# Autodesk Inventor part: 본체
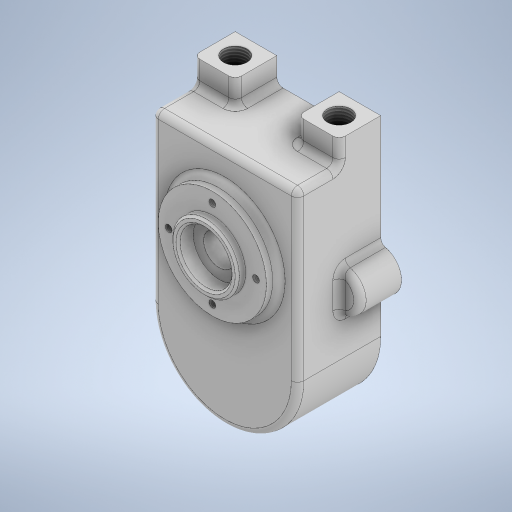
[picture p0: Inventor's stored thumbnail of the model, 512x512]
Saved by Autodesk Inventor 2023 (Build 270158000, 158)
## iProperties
Created: 2024-03
Part Number: 본체
Material: 일반
Document SubType Name: Modeling
Designer: asung
Density: 1 g/cm^3
Appearance: 기본값
Author: asung
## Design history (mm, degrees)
sketch "스케치1"
  geometry: L1 (-35, 40)-(35, 40); L2 (35, 40)-(35, -40); L3 (35, -40)-(-35, -40); L4 (-35, -40)-(-35, 40); L5 (-35, 40)-(35, -40); L6 (35, 40)-(-35, -40); A1 r 35 centre (0, -40) between (-35, -40) and (35, -40); 1 further point
  constraints: 12 end point, 2 midpoint, 2 parallel, 2 point on circle, 1 centre point, 1 horizontal, 1 perpendicular
  dimensions: "d0" = 70 distance of L2.end L3.end; "d1" = 80 distance of L1.end L2.end; "d2" = 35 radius of A1
extrude "돌출1" new body sketch "스케치1" distance "d3" = 40; taper "d4" = 0 deg
sketch "스케치2"
  geometry: L1 (-35, -40)-(-35, 40) reference; L2 (35, 40)-(35, -40) reference; L3 (-35, 40)-(35, 40) reference; L4 (0, 40)-(0, 0); L5 (0, 0)-(0, -40); L6 (-14, -11.314)-(-14, -28.686); L7 (14, -11.314)-(14, -28.686); A1 r 35 centre (0, -40) between (-35, -40) and (35, -40) reference; A2 r 18 centre (0, 0) between (14, -11.314) and (-14, -11.314); A3 r 18 centre (0, -40) between (-14, -28.686) and (14, -28.686); 3 further points
  constraints: 8 end point, 4 point on circle, 2 centre point, 2 coincident, 2 parallel, 2 vertical, 1 midpoint, 1 symmetric about line
  dimensions: "d12" = 40 distance of L4.start L4.end; "d13" = 36 diameter of A2; "d14" = 40 distance of L5.start L5.end (derived); "d15" = 36 diameter of A3; "d17" = 14 distance between parallel lines of L4 L7; "d18" = 28 distance between parallel lines of L6 L7; "d19" = 0 distance from line of point (14, -7) L7; "d20" = 0 distance from line of point (14, -35.376) L7; "d21" = 35.8469 distance of L5.end point (14, -7); "d22" = 14.74401 distance of L5.end point (14, -35.376)
extrude "돌출2" cut sketch "스케치2" distance "d23" = 20; taper "d24" = 0 deg
sketch "스케치3"
  geometry: L1 (70, -20)-(50, -20); L2 (50, -20)-(50, 0); L3 (50, 0)-(70, 0); L4 (70, 0)-(70, -20); L5 (70, 0)-(0, 0) reference; L6 (20, -20)-(0, -20); L7 (0, -20)-(0, 0); L8 (0, 0)-(20, 0); L9 (20, 0)-(20, -20); 3 further points
  constraints: 16 end point, 4 parallel, 2 horizontal, 2 perpendicular, 1 coincident, 1 midpoint, 1 point on line
  dimensions: "d25" = 20 distance of L2.end L3.end; "d26" = 20 distance of L1.end L2.end; "d27" = 20 distance of L5.end L8.end; "d28" = 20 distance of L5.end L6.end
extrude "돌출3" join sketch "스케치3" distance "d29" = 12; taper "d30" = 0 deg
fillet "모깎기1" dims "d31" = 3
fillet "모깎기2" dims "d32" = 3
sketch "스케치4"
  geometry: L1 (-14, -28.686)-(-14, -11.314) reference; L2 (14, -11.314)-(14, -28.686) reference; L3 (-35, -40)-(-35, 52) reference; L4 (35, -40)-(35, 52) reference; L5 (15, 52)-(35, 52) reference; L6 (15, 43)-(15, 52) reference; L7 (-12, 40)-(12, 40) reference; L8 (-15, 43)-(-15, 52) reference; L9 (-35, 52)-(-15, 52) reference; L10 (-35, 52)-(-35, -11.5); L11 (0, 40)-(0, 29.195); A1 r 18 centre (0, -40) between (-14, -28.686) and (14, -28.686) reference; A2 r 18 centre (0, 0) between (14, -11.314) and (-14, -11.314) reference; A3 r 35 centre (0, -40) between (-35, -40) and (35, -40) reference; A4 r 3 centre (12, 43) between (12, 40) and (15, 43) reference; A5 r 3 centre (-12, 43) between (-15, 43) and (-12, 40) reference; A6 r 10 centre (-35, -11.5) between (-35, -1.5) and (-35, -21.5); A7 r 10 centre (35, -11.5) between (35, -21.5) and (35, -1.5); 4 further points
  constraints: 4 end point, 4 point on circle, 3 point on line, 3 symmetric about line, 2 centre point, 1 coincident, 1 midpoint, 1 vertical, 1 other
  dimensions: "d33" = 63.5 distance of L3.end L10.end; "d34" = 10 radius of A6
extrude "돌출4" join sketch "스케치4" distance "d35" = 20; taper "d36" = 0 deg
fillet "모깎기3" dims "d37" = 3
fillet "모깎기4" dims "d38" = 3
sketch "스케치5"
  geometry: L1 (-14, -28.686)-(-14, -11.314) reference; L2 (14, -11.314)-(14, -28.686) reference; L3 (-35, -40)-(-35, -24.149) reference; L4 (35, -40)-(35, -24.149) reference; L5 (35, 1.149)-(35, 52) reference; L6 (15, 52)-(35, 52) reference; L7 (15, 43)-(15, 52) reference; L8 (-12, 40)-(12, 40) reference; L9 (-15, 43)-(-15, 52) reference; L10 (-35, 52)-(-15, 52) reference; L11 (-35, 1.149)-(-35, 52) reference; L12 (0, -40)-(0, -66); A1 r 18 centre (0, -40) between (-14, -28.686) and (14, -28.686) reference; A2 r 18 centre (0, 0) between (14, -11.314) and (-14, -11.314) reference; A3 r 35 centre (0, -40) between (-35, -40) and (35, -40) reference; A4 r 3 centre (38, -24.149) between (37.308, -21.23) and (35, -24.149) reference; A5 r 10 centre (35, -11.5) between (37.308, -21.23) and (37.308, -1.77) reference; A6 r 3 centre (38, 1.149) between (35, 1.149) and (37.308, -1.77) reference; A7 r 3 centre (12, 43) between (12, 40) and (15, 43) reference; A8 r 3 centre (-12, 43) between (-15, 43) and (-12, 40) reference; A9 r 3 centre (-38, 1.149) between (-37.308, -1.77) and (-35, 1.149) reference; A10 r 10 centre (-35, -11.5) between (-37.308, -1.77) and (-37.308, -21.23) reference; A11 r 3 centre (-38, -24.149) between (-35, -24.149) and (-37.308, -21.23) reference; 3 further points
  constraints: 2 end point, 1 coincident, 1 vertical
  dimensions: "d54" = 26 distance of L12.start L12.end
  node "투영된 루프3"
hole "구멍2" sketch "스케치5" diameter "d47" = 4.134; stored, may be unused: countersink angle "d51" = 90 deg, drill point angle "d53" = 118 deg; dims "d48" = 10, "d49" = 4, "d50" = 2, "d52" = 12
sketch "스케치7"
  geometry: C1 r 26 at (0, 0); 1 further point
  constraints: 1 centre point, 1 coincident
  dimensions: "d55" = 52 diameter of C1
extrude "돌출5" join sketch "스케치7" distance "d56" = 6; taper "d57" = 0 deg
sketch "스케치8"
  geometry: C1 r 16 at (0, 0); 1 further point
  constraints: 1 centre point, 1 coincident
  dimensions: "d58" = 32 diameter of C1
extrude "돌출6" join sketch "스케치8" distance "d59" = 4; taper "d60" = 0 deg
fillet "모깎기5" dims "d61" = 3
sketch "스케치9"
  geometry: C1 r 16 at (0, 0) reference; 2 further points
  constraints: 1 coincident
hole "구멍3" sketch "스케치9" at (0, 0) diameter "d62" = 15; stored, may be unused: countersink angle "d66" = 90 deg, drill point angle "d68" = 0 deg; dims "d63" = 10, "d64" = 25, "d65" = 7.3, "d67" = 20
sketch "스케치10"
  geometry: A1 r 18 centre (0, -40) between (-14, -28.686) and (14, -28.686) reference; 2 further points
  constraints: 1 coincident
hole "구멍4" sketch "스케치10" at (0, -40) diameter "d69" = 20; stored, may be unused: countersink angle "d73" = 90 deg, drill point angle "d75" = 120 deg; dims "d70" = 6, "d71" = 20, "d72" = 20, "d74" = 10
chamfer "모따기1" distance "d76" = 1; stored, may be unused: second distance "d77" = 2, angle "d78" = 45 deg
sketch "스케치11" dims "d79" = 42
  geometry: 3 further points
  constraints: 1 coincident, 1 vertical alignment, 2 other
hole "구멍5" sketch "스케치11" at (0, 21) diameter "d80" = 3.242; stored, may be unused: countersink angle "d84" = 90 deg, drill point angle "d86" = 120 deg; dims "d81" = 8, "d82" = 4, "d83" = 2, "d85" = 10
sketch "스케치12"
  geometry: A1 r 18 centre (0, 0) between (14, -11.314) and (-14, -11.314) reference; 2 further points
  constraints: 1 coincident
hole "구멍6" sketch "스케치12" at (0, 0) diameter "d90" = 20; stored, may be unused: countersink angle "d94" = 90 deg, drill point angle "d96" = 0 deg; dims "d91" = 6, "d92" = 25, "d93" = 7.3, "d95" = 10
sketch "스케치13"
  geometry: 1 further point
sketch "스케치14"
  geometry: L1 (0, 0)-(0, 26); 1 further point
  constraints: 2 end point, 1 coincident, 1 vertical
  dimensions: "d97" = 26 distance of L1.start L1.end
hole "구멍7" sketch "스케치14" at (0, 26) diameter "d98" = 4.134; stored, may be unused: countersink angle "d102" = 90 deg, drill point angle "d104" = 118 deg; dims "d99" = 10, "d100" = 25, "d101" = 7.3, "d103" = 12
sketch "스케치16"
  geometry: L1 (70, 0)-(50, 0) reference; L2 (60, 0)-(60, -10); 2 further points
  constraints: 2 end point, 1 coincident, 1 midpoint, 1 vertical
  dimensions: "d105" = 10 distance of L2.start L2.end
hole "구멍8" sketch "스케치16" at (60, -10) diameter "d106" = 10.5; stored, may be unused: countersink angle "d112" = 90 deg, drill point angle "d114" = 118 deg; dims "d107" = 11, "d108" = 0.62479, "d109" = 10.589, "d110" = 4, "d111" = 2, "d113" = 16
chamfer "모따기2" distance "d115" = 1; stored, may be unused: second distance "d116" = 2, angle "d117" = 45 deg
chamfer "모따기3" distance "d118" = 1; stored, may be unused: second distance "d119" = 2, angle "d120" = 45 deg
chamfer "모따기4" distance "d121" = 1; stored, may be unused: second distance "d122" = 2, angle "d123" = 45 deg
feature "ƀ耀Ƃ耀Ƅ耀Ɔ耀ƈ耀Ɗ耀ƌ耀Ǝ耀" dims "d0" = 70, "d1" = 80, "d2" = 35, "d3" = 40, "d4" = 0, "d6" = 36, "d8" = 36, "d12" = 40, "d13" = 36, "d14" = 40 (derived), "d15" = 36, "d17" = 14, "d18" = 28, "d19" = 0, "d20" = 0, "d21" = 35.8469, "d22" = 14.74401, "d23" = 20, "d24" = 0, "d25" = 20, "d26" = 20, "d27" = 20, "d28" = 20, "d29" = 12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
node "솔리드1"
mirror "미러1"
pattern_circular "원형 패턴1" dims angle "d88" = 360 deg
mirror "미러2"
node "투영된 루프1"
node "투영된 루프2"
feature "A9D066F2-1C7D-4E18-AEED-F7BC21143FA4" dims "d62" = 15, "d63" = 10, "d64" = 25, "d65" = 7.3, "d66" = 90 deg, "d67" = 20, "d68" = 0
